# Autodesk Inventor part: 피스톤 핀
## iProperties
Manager: KYOUNG IL JANG
Company: 한국ATC센터
Created: 2012-10
Part Number: 피스톤 핀
Document SubType Name: Modeling
Density: 1 g/cm^3
Checked By: KYOUNG IL JANG
Vendor: CBT Solutions
Designer: KYOUNG IL JANG
Author: KYOUNG IL JANG
